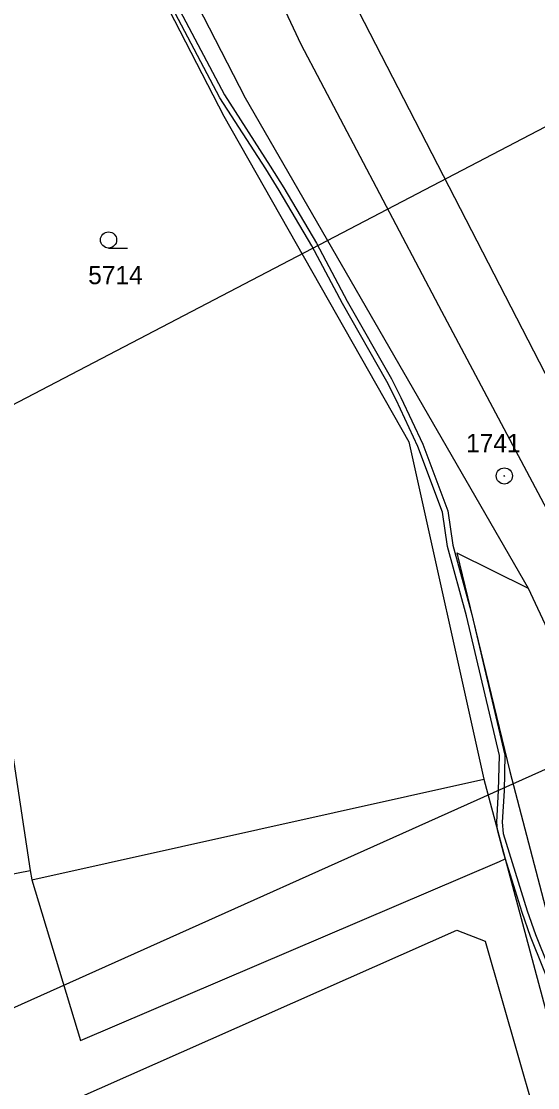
# Model space of a CAD drawing. Extents: x -735092 to -733385, y -1122435 to -1118992.
# Drawn here: x -734319.7 to -734271.7, y -1121325.7 to -1121226.6 of the extents above; entities that cross this region are included whole.
import ezdxf

# ---------------------------------------------------------------- set-up
doc = ezdxf.new("R2010")
doc.units = 0
for name, color, linetype in [('Vrstva 1', 7, 'Continuous'), ('Vrstva 10', 7, 'Continuous'), ('Vrstva 12', 7, 'Continuous'), ('Vrstva 17', 7, 'Continuous'), ('Vrstva 18', 7, 'Continuous'), ('Vrstva 25', 7, 'Continuous'), ('Vrstva 27', 7, 'Continuous'), ('Vrstva 4', 7, 'Continuous')]:
    doc.layers.add(name, color=color, linetype=linetype)

msp = doc.modelspace()

# ---------------------------------------------------------------- linework, layer by layer
at = {"layer": 'Vrstva 1'}
for points in [[(-734339.29, -1121169.94), (-734318.83, -1121305.55)], [(-734319.41, -1121193.81), (-734298.87, -1121233.77)], [(-734321.8, -1121194.82), (-734300.85, -1121235.47)], [(-734288.89, -1121224.69), (-734266.35, -1121268.46)], [(-734298.87, -1121233.77), (-734281.06, -1121264.67)], [(-734300.85, -1121235.47), (-734283.68, -1121265.72)], [(-734281.06, -1121264.67), (-734272.61, -1121279.33)], [(-734283.68, -1121265.72), (-734276.72, -1121297.06)], [(-734279.21, -1121276.03), (-734274.3, -1121296.34)], [(-734279.21, -1121276.03), (-734272.61, -1121279.33)], [(-734272.61, -1121279.33), (-734227.25, -1121376.46)], [(-734318.68, -1121306.41), (-734276.72, -1121297.06)], [(-734276.72, -1121297.06), (-734274.73, -1121304.47)], [(-734274.3, -1121296.34), (-734258.93, -1121355.16)], [(-734274.73, -1121304.47), (-734258.22, -1121366.04)], [(-734322.51, -1121306.27), (-734318.83, -1121305.55)], [(-734318.83, -1121305.55), (-734318.68, -1121306.41)]]:
    msp.add_lwpolyline(points, dxfattribs=at)
at = {"layer": 'Vrstva 10'}
for points in [[(-734293.69, -1121228.8), (-734329.57, -1121152.33)], [(-734280.89, -1121253.09), (-734293.69, -1121228.8)], [(-734266.9, -1121279.43), (-734280.89, -1121253.09)]]:
    msp.add_lwpolyline(points, dxfattribs=at)
at = {"layer": 'Vrstva 12'}
for points in [[(-734359.03, -1121282.41), (-734007.75, -1121098.86)], [(-734360.81, -1121336.42), (-734230.19, -1121277.82)]]:
    msp.add_lwpolyline(points, dxfattribs=at)
at = {"layer": 'Vrstva 25'}
msp.add_lwpolyline([(-734311.56, -1121247.71), (-734309.81, -1121247.71)], dxfattribs=at)
for centre, radius in [((-734311.56, -1121246.96), 0.75), ((-734274.81, -1121268.89), 0.75), ((-734274.81, -1121268.89), 0.032)]:
    msp.add_circle(centre, radius, dxfattribs=at)
at = {"layer": 'Vrstva 27'}
for points in [[(-734304.93, -1121225.65), (-734300.78, -1121233.49), (-734296.54, -1121240.1), (-734295.29, -1121242.11), (-734292.25, -1121247.26), (-734289.4, -1121252.64), (-734285.29, -1121259.88), (-734284.42, -1121261.59), (-734282.37, -1121265.94), (-734280.07, -1121272.13), (-734279.6, -1121275.33), (-734277.84, -1121281.77), (-734274.75, -1121294.82), (-734274.84, -1121298.14), (-734275.02, -1121301.05), (-734274.91, -1121302.12), (-734272.68, -1121309.3), (-734271.91, -1121311.49), (-734268.42, -1121320.21), (-734267.58, -1121322.71), (-734264.12, -1121336.62)], [(-734264.6, -1121336.74), (-734268.06, -1121322.85), (-734268.89, -1121320.39), (-734272.37, -1121311.67), (-734273.16, -1121309.46), (-734274.85, -1121304.01), (-734275.45, -1121301.78), (-734275.52, -1121301.06), (-734275.34, -1121298.12), (-734275.25, -1121294.88), (-734278.32, -1121281.89), (-734280.09, -1121275.43), (-734280.55, -1121272.25), (-734282.83, -1121266.14), (-734284.86, -1121261.81), (-734285.73, -1121260.12), (-734289.84, -1121252.88), (-734292.69, -1121247.5), (-734295.71, -1121242.37), (-734296.96, -1121240.36), (-734301.22, -1121233.75), (-734305.37, -1121225.89)]]:
    msp.add_lwpolyline(points, dxfattribs=at)
at = {"layer": 'Vrstva 4'}
for points in [[(-734314.18, -1121321.36), (-734275.27, -1121304.7)], [(-734275.27, -1121304.7), (-734274.73, -1121304.47)], [(-734318.68, -1121306.41), (-734314.18, -1121321.36)], [(-734342.88, -1121339.31), (-734279.23, -1121311.1)], [(-734279.23, -1121311.1), (-734276.6, -1121312.13)], [(-734276.6, -1121312.13), (-734269.08, -1121338.39)]]:
    msp.add_lwpolyline(points, dxfattribs=at)

# ---------------------------------------------------------------- texts
at = {"layer": 'Vrstva 17'}
msp.add_text('1741', height=1.7, dxfattribs=at).set_placement((-734278.36, -1121266.68))
at = {"layer": 'Vrstva 18'}
msp.add_text('5714', height=1.7, dxfattribs=at).set_placement((-734313.45, -1121251.07))

doc.saveas('drawing.dxf')
